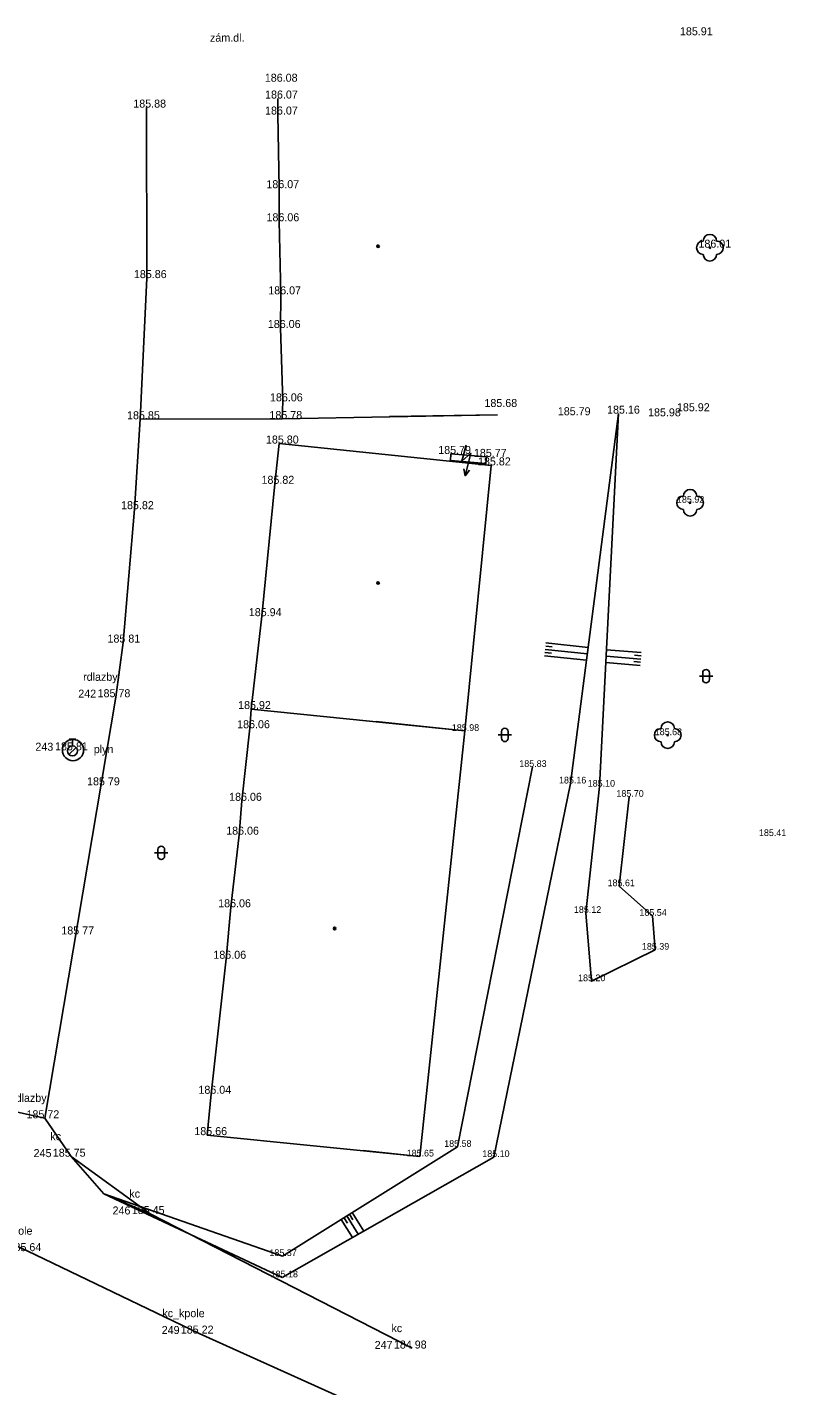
# Model space of a CAD drawing. Extents: x -598527 to -598215, y -1172822 to -1172560.
# Drawn here: x -598243.4 to -598215, y -1172610.6 to -1172559.7 of the extents above; entities that cross this region are included whole.
import ezdxf

# ---------------------------------------------------------------- set-up
doc = ezdxf.new("R2010")
doc.units = 0
for name, color, linetype in [('Body', 7, 'Continuous'), ('Body čísla', 7, 'Continuous'), ('Budovy', 7, 'Continuous'), ('Budovy_znacky', 7, 'Continuous'), ('Chodniky', 7, 'Continuous'), ('Hrana svahu', 7, 'Continuous'), ('Kody', 7, 'Continuous'), ('Pata svahu', 7, 'Continuous'), ('PATTERN_CLASS', 7, 'Continuous'), ('Povrchy_popis', 7, 'Continuous'), ('PRIS', 7, 'Continuous'), ('Sachty', 7, 'Continuous'), ('Stromy', 7, 'Continuous'), ('Vstupy', 7, 'Continuous'), ('Výšky', 7, 'Continuous'), ('Značky kultur', 7, 'Continuous'), ('Šrafy', 7, 'Continuous')]:
    doc.layers.add(name, color=color, linetype=linetype)

msp = doc.modelspace()

# ---------------------------------------------------------------- linework, layer by layer
at = {"layer": 'Body'}
for p, q in [((-598218.54, -1172560.01), (-598218.54, -1172560.01)), ((-598234.04, -1172561.75), (-598234.04, -1172561.75)), ((-598238.96, -1172562.72), (-598238.96, -1172562.72)), ((-598234.04, -1172562.38), (-598234.04, -1172562.38)), ((-598234.04, -1172562.98), (-598234.04, -1172562.98)), ((-598233.99, -1172565.74), (-598233.99, -1172565.74)), ((-598233.98, -1172566.98), (-598233.98, -1172566.98)), ((-598217.85, -1172567.97), (-598217.85, -1172567.97)), ((-598238.94, -1172569.11), (-598238.94, -1172569.11)), ((-598233.92, -1172569.72), (-598233.92, -1172569.72)), ((-598233.93, -1172570.98), (-598233.93, -1172570.98)), ((-598233.85, -1172573.73), (-598233.85, -1172573.73)), ((-598225.81, -1172573.94), (-598225.81, -1172573.94)), ((-598239.19, -1172574.4), (-598239.19, -1172574.4)), ((-598233.87, -1172574.39), (-598233.87, -1172574.39)), ((-598223.07, -1172574.25), (-598223.07, -1172574.25)), ((-598221.27, -1172574.19), (-598221.27, -1172574.19)), ((-598219.68, -1172574.29), (-598219.68, -1172574.29)), ((-598218.59, -1172574.1), (-598218.59, -1172574.1)), ((-598233.99, -1172575.31), (-598233.99, -1172575.31)), ((-598227.55, -1172575.7), (-598227.55, -1172575.7)), ((-598226.22, -1172575.81), (-598226.22, -1172575.81)), ((-598226.04, -1172576.13), (-598226.04, -1172576.13)), ((-598234.15, -1172576.82), (-598234.15, -1172576.82)), ((-598218.59, -1172577.53), (-598218.59, -1172577.53)), ((-598239.41, -1172577.77), (-598239.41, -1172577.77)), ((-598234.64, -1172581.78), (-598234.64, -1172581.78)), ((-598239.83, -1172582.77), (-598239.83, -1172582.77)), ((-598240.1, -1172584.81), (-598240.1, -1172584.81)), ((-598240.1, -1172584.81), (-598240.1, -1172584.81)), ((-598235.03, -1172585.26), (-598235.03, -1172585.26)), ((-598235.08, -1172585.98), (-598235.08, -1172585.98)), ((-598227.03, -1172586.08), (-598227.03, -1172586.08)), ((-598219.43, -1172586.24), (-598219.43, -1172586.24)), ((-598241.71, -1172586.8), (-598241.71, -1172586.8)), ((-598241.71, -1172586.8), (-598241.71, -1172586.8)), ((-598224.49, -1172587.43), (-598224.49, -1172587.43)), ((-598240.63, -1172588.12), (-598240.63, -1172588.12)), ((-598223.07, -1172588.05), (-598223.07, -1172588.05)), ((-598221.99, -1172588.17), (-598221.99, -1172588.17)), ((-598235.38, -1172588.7), (-598235.38, -1172588.7)), ((-598220.87, -1172588.55), (-598220.87, -1172588.55)), ((-598235.49, -1172589.97), (-598235.49, -1172589.97)), ((-598215.58, -1172590.02), (-598215.58, -1172590.02)), ((-598221.25, -1172591.9), (-598221.25, -1172591.9)), ((-598235.79, -1172592.69), (-598235.79, -1172592.69)), ((-598222.5, -1172592.9), (-598222.5, -1172592.9)), ((-598220, -1172593.01), (-598220, -1172593.01)), ((-598241.6, -1172593.71), (-598241.6, -1172593.71)), ((-598219.9, -1172594.28), (-598219.9, -1172594.28)), ((-598235.97, -1172594.62), (-598235.97, -1172594.62)), ((-598222.29, -1172595.46), (-598222.29, -1172595.46)), ((-598236.53, -1172599.68), (-598236.53, -1172599.68)), ((-598242.76, -1172600.59), (-598242.76, -1172600.59)), ((-598242.76, -1172600.59), (-598242.76, -1172600.59)), ((-598236.68, -1172601.23), (-598236.68, -1172601.23)), ((-598227.31, -1172601.67), (-598227.31, -1172601.67)), ((-598241.78, -1172602.03), (-598241.78, -1172602.03)), ((-598241.78, -1172602.03), (-598241.78, -1172602.03)), ((-598228.72, -1172602.03), (-598228.72, -1172602.03)), ((-598225.94, -1172602.05), (-598225.94, -1172602.05)), ((-598240.55, -1172603.43), (-598240.55, -1172603.43)), ((-598238.82, -1172604.18), (-598238.82, -1172604.18)), ((-598238.82, -1172604.18), (-598238.82, -1172604.18)), ((-598233.86, -1172605.76), (-598233.86, -1172605.76)), ((-598233.87, -1172606.56), (-598233.87, -1172606.56)), ((-598236.98, -1172608.66), (-598236.98, -1172608.66)), ((-598236.98, -1172608.66), (-598236.98, -1172608.66)), ((-598229, -1172609.22), (-598229, -1172609.22)), ((-598229, -1172609.22), (-598229, -1172609.22))]:
    msp.add_line(p, q, dxfattribs=at)
at = {"layer": 'Budovy'}
for p, q in [((-598225.806, -1172574.24), (-598229.853, -1172574.298)), ((-598227.03, -1172586.08), (-598226.04, -1172576.13)), ((-598227.03, -1172586.08), (-598230.35, -1172585.728)), ((-598227.03, -1172586.08), (-598228.72, -1172602.03)), ((-598228.72, -1172602.03), (-598230.837, -1172601.806))]:
    msp.add_line(p, q, dxfattribs=at)
for points in [[(-598234.04, -1172562.38), (-598234.04, -1172562.98), (-598233.99, -1172565.74), (-598233.98, -1172566.98), (-598233.92, -1172569.72), (-598233.93, -1172570.98), (-598233.85, -1172573.73), (-598233.87, -1172574.39), (-598225.806, -1172574.24)], [(-598226.04, -1172576.13), (-598233.99, -1172575.31), (-598234.15, -1172576.82), (-598234.64, -1172581.78), (-598235.03, -1172585.26), (-598227.03, -1172586.08)], [(-598235.03, -1172585.26), (-598235.08, -1172585.98), (-598235.38, -1172588.7), (-598235.49, -1172589.97), (-598235.79, -1172592.69), (-598235.97, -1172594.62), (-598236.53, -1172599.68), (-598236.68, -1172601.23), (-598228.72, -1172602.03)]]:
    msp.add_lwpolyline(points, dxfattribs=at)
at = {"layer": 'Budovy_znacky'}
for centre, radius in [((-598230.278, -1172567.914), 0.045), ((-598230.278, -1172567.914), 0.0199), ((-598230.278, -1172580.536), 0.045), ((-598230.278, -1172580.536), 0.0199), ((-598231.91, -1172593.486), 0.045), ((-598231.91, -1172593.486), 0.0199)]:
    msp.add_circle(centre, radius, dxfattribs=at)
at = {"layer": 'Chodniky'}
for p, q in [((-598238.96, -1172562.72), (-598238.94, -1172569.11)), ((-598238.94, -1172569.11), (-598239.19, -1172574.4)), ((-598239.19, -1172574.4), (-598239.41, -1172577.77)), ((-598239.19, -1172574.4), (-598233.87, -1172574.39)), ((-598239.41, -1172577.77), (-598239.83, -1172582.77)), ((-598239.83, -1172582.77), (-598240.1, -1172584.81)), ((-598233.87, -1172606.56), (-598240.55, -1172603.43))]:
    msp.add_line(p, q, dxfattribs=at)
at = {"layer": 'Hrana svahu'}
for p, q in [((-598224.49, -1172587.43), (-598227.31, -1172601.67)), ((-598220.87, -1172588.55), (-598221.25, -1172591.9)), ((-598221.25, -1172591.9), (-598220, -1172593.01)), ((-598227.31, -1172601.67), (-598233.86, -1172605.76)), ((-598233.86, -1172605.76), (-598240.55, -1172603.43))]:
    msp.add_line(p, q, dxfattribs=at)
at = {"layer": 'Pata svahu'}
for p, q in [((-598221.27, -1172574.19), (-598223.07, -1172588.05)), ((-598221.27, -1172574.19), (-598221.99, -1172588.17)), ((-598223.07, -1172588.05), (-598225.94, -1172602.05)), ((-598221.99, -1172588.17), (-598222.5, -1172592.9)), ((-598219.9, -1172594.28), (-598220, -1172593.01)), ((-598225.94, -1172602.05), (-598233.87, -1172606.56))]:
    msp.add_line(p, q, dxfattribs=at)
msp.add_lwpolyline([(-598222.5, -1172592.9), (-598222.29, -1172595.46), (-598219.9, -1172594.28)], dxfattribs=at)
at = {"layer": 'PATTERN_CLASS'}
msp.add_line((-598242.76, -1172600.59), (-598240.1, -1172584.81), dxfattribs=at)
msp.add_line((-598242.76, -1172600.59), (-598240.1, -1172584.81), dxfattribs=at)
for points in [[(-598229, -1172609.22), (-598238.82, -1172604.18), (-598241.78, -1172602.03), (-598242.76, -1172600.59), (-598248.3, -1172599.38), (-598248.331, -1172599.375)], [(-598229, -1172609.22), (-598238.82, -1172604.18), (-598240.55, -1172603.43), (-598241.78, -1172602.03), (-598242.76, -1172600.59), (-598248.3, -1172599.38), (-598248.331, -1172599.375)], [(-598250.11, -1172612.28), (-598247.61, -1172606.36), (-598246.923, -1172605.269), (-598246.42, -1172604.864), (-598245.775, -1172604.644), (-598245.325, -1172604.707), (-598243.43, -1172605.57), (-598236.98, -1172608.66), (-598229.73, -1172611.94)]]:
    msp.add_lwpolyline(points, dxfattribs=at)
msp.add_circle((-598241.71, -1172586.8), 0.398, dxfattribs=at)
msp.add_circle((-598241.71, -1172586.8), 0.398, dxfattribs=at)
at = {"layer": 'PRIS'}
msp.add_lwpolyline([(-598227.55, -1172575.7), (-598226.22, -1172575.81), (-598226.241, -1172576.059), (-598227.571, -1172575.949)], close=True, dxfattribs=at)
at = {"layer": 'Sachty'}
for p, q in [((-598241.859, -1172586.966), (-598241.594, -1172586.701)), ((-598241.855, -1172586.393), (-598241.605, -1172586.393)), ((-598241.73, -1172586.643), (-598241.73, -1172586.393))]:
    msp.add_line(p, q, dxfattribs=at)
msp.add_circle((-598241.73, -1172586.83), 0.188, dxfattribs=at)
at = {"layer": 'Stromy'}
for centre in [(-598217.85, -1172567.97), (-598218.59, -1172577.53), (-598219.43, -1172586.24)]:
    msp.add_circle(centre, 0.025, dxfattribs=at)
for centre, start, end in [((-598218.1, -1172567.97), 90, 270), ((-598217.85, -1172567.72), 0, 180), ((-598217.6, -1172567.97), 270, 90), ((-598217.85, -1172568.22), 180, 0), ((-598218.59, -1172577.28), 0, 180), ((-598218.84, -1172577.53), 90, 270), ((-598218.34, -1172577.53), 270, 90), ((-598218.59, -1172577.78), 180, 0), ((-598219.68, -1172586.24), 90, 270), ((-598219.43, -1172585.99), 0, 180), ((-598219.18, -1172586.24), 270, 90), ((-598219.43, -1172586.49), 180, 0)]:
    msp.add_arc(centre, 0.25, start, end, dxfattribs=at)
at = {"layer": 'Vstupy'}
for p, q in [((-598234.04, -1172562.98), (-598233.99, -1172565.74)), ((-598233.98, -1172566.98), (-598233.92, -1172569.72)), ((-598233.93, -1172570.98), (-598233.85, -1172573.73)), ((-598234.15, -1172576.82), (-598234.64, -1172581.78)), ((-598235.08, -1172585.98), (-598235.38, -1172588.7)), ((-598235.49, -1172589.97), (-598235.79, -1172592.69)), ((-598235.97, -1172594.62), (-598236.53, -1172599.68))]:
    msp.add_line(p, q, dxfattribs=at)
at = {"layer": 'Značky kultur'}
for p, q in [((-598218.245, -1172584.029), (-598217.745, -1172584.029)), ((-598218.12, -1172583.904), (-598218.12, -1172584.154)), ((-598217.87, -1172583.904), (-598217.87, -1172584.154)), ((-598225.657, -1172586.107), (-598225.657, -1172586.357)), ((-598225.407, -1172586.107), (-598225.407, -1172586.357)), ((-598225.782, -1172586.232), (-598225.282, -1172586.232)), ((-598238.651, -1172590.653), (-598238.151, -1172590.653)), ((-598238.526, -1172590.528), (-598238.526, -1172590.778)), ((-598238.276, -1172590.528), (-598238.276, -1172590.778))]:
    msp.add_line(p, q, dxfattribs=at)
for points in [[(-598226.982, -1172575.369), (-598227.139, -1172575.974), (-598226.803, -1172575.673), (-598227.022, -1172576.52)], [(-598227.067, -1172576.256), (-598227.022, -1172576.52), (-598226.855, -1172576.311)]]:
    msp.add_lwpolyline(points, dxfattribs=at)
for centre, start, end in [((-598217.995, -1172583.904), 0, 180), ((-598217.995, -1172584.154), 180, 0), ((-598225.532, -1172586.107), 0, 180), ((-598225.532, -1172586.357), 180, 0), ((-598238.401, -1172590.528), 0, 180), ((-598238.401, -1172590.778), 180, 0)]:
    msp.add_arc(centre, 0.125, start, end, dxfattribs=at)
at = {"layer": 'Šrafy'}
for p, q in [((-598224.028, -1172583.143), (-598223.78, -1172583.17)), ((-598224.015, -1172583.024), (-598222.439, -1172583.193)), ((-598224.002, -1172582.904), (-598223.754, -1172582.931)), ((-598223.99, -1172582.785), (-598222.408, -1172582.955)), ((-598220.419, -1172583.146), (-598221.726, -1172583.037)), ((-598224.041, -1172583.262), (-598222.47, -1172583.432)), ((-598220.459, -1172583.625), (-598221.75, -1172583.517)), ((-598220.439, -1172583.386), (-598221.738, -1172583.277)), ((-598220.449, -1172583.505), (-598220.698, -1172583.484)), ((-598220.429, -1172583.266), (-598220.678, -1172583.245)), ((-598231.66, -1172604.386), (-598231.237, -1172605.063)), ((-598231.558, -1172604.323), (-598231.426, -1172604.535)), ((-598231.456, -1172604.259), (-598231.028, -1172604.944)), ((-598231.354, -1172604.195), (-598231.222, -1172604.407)), ((-598231.253, -1172604.132), (-598230.82, -1172604.825))]:
    msp.add_line(p, q, dxfattribs=at)

# ---------------------------------------------------------------- texts
at = {"layer": 'Body čísla'}
for s, p in [('242', (-598241.511, -1172584.833)), ('243', (-598243.117, -1172586.823)), ('245', (-598243.185, -1172602.053)), ('246', (-598240.227, -1172604.203)), ('249', (-598238.386, -1172608.683)), ('247', (-598230.408, -1172609.243))]:
    msp.add_text(s, height=0.3, dxfattribs=at).set_placement(p)
at = {"layer": 'Kody'}
for s, p in [('rdlazby', (-598241.33, -1172584.203)), ('rdlazby', (-598243.99, -1172599.983)), ('kc', (-598242.558, -1172601.423)), ('kc', (-598239.598, -1172603.573)), ('kc_kpole', (-598244.811, -1172604.963)), ('kc_kpole', (-598238.361, -1172608.053)), ('kc', (-598229.778, -1172608.613))]:
    msp.add_text(s, height=0.3, dxfattribs=at).set_placement(p)
at = {"layer": 'PATTERN_CLASS'}
msp.add_text('plyn', height=0.3, dxfattribs=at).set_placement((-598240.93, -1172586.914))
msp.add_text('plyn', height=0.3, dxfattribs=at).set_placement((-598240.93, -1172586.914))
at = {"layer": 'Povrchy_popis'}
msp.add_text('zám.dl.', height=0.3, dxfattribs=at).set_placement((-598236.577, -1172560.249))
at = {"layer": 'Výšky'}
for s, height, p in [('185.91', 0.3, (-598218.972, -1172560.01)), ('186.08', 0.3, (-598234.523, -1172561.75)), ('186.07', 0.3, (-598234.514, -1172562.38)), ('185.88', 0.3, (-598239.45, -1172562.72)), ('186.07', 0.3, (-598234.514, -1172562.98)), ('186.07', 0.3, (-598234.464, -1172565.74)), ('186.06', 0.3, (-598234.46, -1172566.98)), ('186.01', 0.3, (-598218.279, -1172567.97)), ('185.86', 0.3, (-598239.427, -1172569.11)), ('186.07', 0.3, (-598234.394, -1172569.72)), ('186.06', 0.3, (-598234.41, -1172570.98)), ('186.06', 0.3, (-598234.33, -1172573.73)), ('185.68', 0.3, (-598226.296, -1172573.94)), ('185.79', 0.3, (-598223.547, -1172574.25)), ('185.16', 0.3, (-598221.702, -1172574.19)), ('185.98', 0.3, (-598220.166, -1172574.29)), ('185.92', 0.3, (-598219.084, -1172574.1)), ('185.85', 0.3, (-598239.684, -1172574.4)), ('185.78', 0.3, (-598234.35, -1172574.39)), ('185.80', 0.3, (-598234.481, -1172575.31)), ('185.79', 0.3, (-598228.027, -1172575.7)), ('185.77', 0.3, (-598226.691, -1172575.81)), ('185.82', 0.3, (-598226.538, -1172576.13)), ('185.82', 0.3, (-598234.648, -1172576.82)), ('185.82', 0.3, (-598239.908, -1172577.77)), ('185.92', 0.25, (-598219.084, -1172577.53)), ('185.94', 0.3, (-598235.123, -1172581.78)), ('185 81', 0.3, (-598240.417, -1172582.77)), ('185 78', 0.3, (-598240.788, -1172584.818)), ('185 78', 0.3, (-598240.788, -1172584.818)), ('185.92', 0.3, (-598235.524, -1172585.26)), ('186.06', 0.3, (-598235.56, -1172585.98)), ('185.98', 0.25, (-598227.516, -1172586.08)), ('185.68', 0.25, (-598219.916, -1172586.24)), ('185 81', 0.3, (-598242.381, -1172586.808)), ('185 81', 0.3, (-598242.381, -1172586.808)), ('185.83', 0.25, (-598224.99, -1172587.43)), ('185 79', 0.3, (-598241.182, -1172588.12)), ('185.16', 0.25, (-598223.502, -1172588.05)), ('185.10', 0.25, (-598222.426, -1172588.17)), ('186.06', 0.3, (-598235.86, -1172588.7)), ('185.70', 0.25, (-598221.351, -1172588.55)), ('186.06', 0.3, (-598235.97, -1172589.97)), ('185.41', 0.25, (-598216.012, -1172590.02)), ('185.61', 0.25, (-598221.682, -1172591.9)), ('186.06', 0.3, (-598236.27, -1172592.69)), ('185.12', 0.25, (-598222.943, -1172592.9)), ('185.54', 0.25, (-598220.49, -1172593.01)), ('185 77', 0.3, (-598242.146, -1172593.71)), ('186.06', 0.3, (-598236.45, -1172594.62)), ('185.39', 0.25, (-598220.396, -1172594.28)), ('185.20', 0.25, (-598222.788, -1172595.46)), ('186.04', 0.3, (-598237.01, -1172599.68)), ('185 72', 0.3, (-598243.451, -1172600.598)), ('185 72', 0.3, (-598243.451, -1172600.598)), ('185.66', 0.3, (-598237.163, -1172601.23)), ('185.58', 0.25, (-598227.803, -1172601.67)), ('185 75', 0.3, (-598242.466, -1172602.038)), ('185 75', 0.3, (-598242.466, -1172602.038)), ('185.65', 0.25, (-598229.21, -1172602.03)), ('185.10', 0.25, (-598226.376, -1172602.05)), ('185 45', 0.3, (-598239.506, -1172604.188)), ('185 45', 0.3, (-598239.506, -1172604.188)), ('185 64', 0.3, (-598244.124, -1172605.578)), ('185 64', 0.3, (-598244.124, -1172605.578)), ('185.37', 0.25, (-598234.35, -1172605.76)), ('185.18', 0.25, (-598234.305, -1172606.56)), ('185 22', 0.3, (-598237.671, -1172608.668)), ('185 22', 0.3, (-598237.671, -1172608.668)), ('184 98', 0.3, (-598229.688, -1172609.228)), ('184 98', 0.3, (-598229.688, -1172609.228))]:
    msp.add_text(s, height=height, dxfattribs=at).set_placement(p)

doc.saveas('drawing.dxf')
